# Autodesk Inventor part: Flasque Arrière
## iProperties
Shininess: 64.0
Length Units: 11269
Angle Units: 11279
Time Units: 11290
Mass Units: 11283
Length Display Precision: 3
Angle Display Precision: 2
Compacted: True
Part Number: Flasque Arrière
Document SubType Name: Modeling
Created: 2005-01
Material: Par défaut
Designer: lolo (Laurent Moretti)
Density: 0.0
Volumn: 0.0
Area: 0.0
PropertySet Name: Model Information
Control State: 0
Master: False
Checked Out: False
Author: lolo (Laurent Moretti)
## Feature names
1. Révolution1 [Revolution]
2. Congé1 [Fillet]
3. Congé2 [Fillet]
4. Chanfrein1 [Chamfer]
5. Chanfrein2 [Chamfer]
6. Extrusion1
7. Extrusion2
8. Congé3 [Fillet]
9. Réseau circulaire1 [Circular Pattern]
10. Perçage1 [Hole]
11. Extrusion3
12. Réseau circulaire2 [Circular Pattern]
13. Perçage2 [Hole]
14. Réseau circulaire3 [Circular Pattern]
15. Extrusion4
16. Perçage3 [Hole]
17. Symétrie1 [Mirror]
18. Symétrie2 [Mirror]
